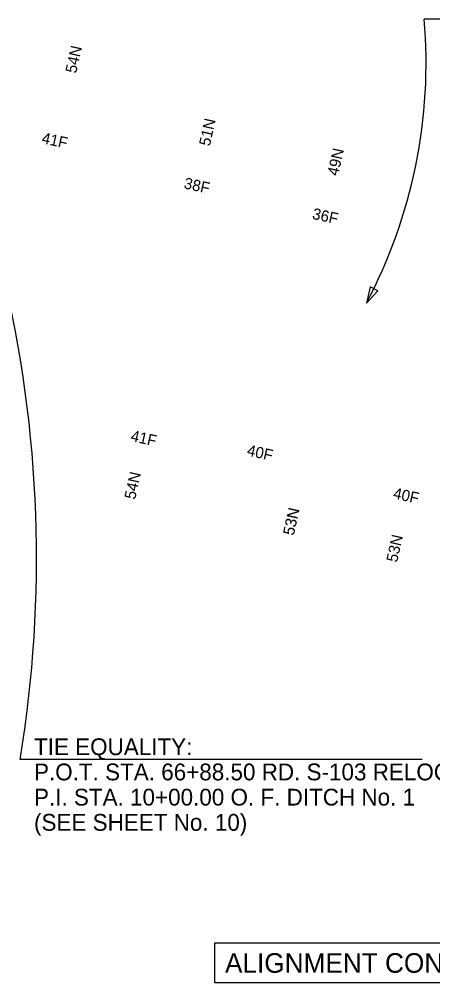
# Model space of a CAD drawing. Extents: x 1964849 to 1967422, y 1116563 to 1122210.
# Drawn here: x 1967021.8 to 1967169.6, y 1118230.2 to 1118574.2 of the extents above; entities that cross this region are included whole.
import ezdxf

# ---------------------------------------------------------------- set-up
doc = ezdxf.new("R2010")
doc.units = 0
for name, color, linetype in [('RD_HC_Data', 7, 'Continuous'), ('RD_PD_TX_CstnLmt', 7, 'Continuous'), ('RD_Sketch1', 7, 'Continuous'), ('RD_TX_Drainage', 7, 'Continuous'), ('RD_TX_Misc1', 7, 'Continuous')]:
    doc.layers.add(name, color=color, linetype=linetype)

msp = doc.modelspace()

# ---------------------------------------------------------------- linework, layer by layer
at = {"layer": 'RD_HC_Data'}
msp.add_line((1967165.81, 1118309.94), (1967022.08, 1118309.94), dxfattribs=at)
msp.add_arc((1966589.37, 1118381.72), 438.62, 350.5812, 13.5141, dxfattribs=at)
at = {"layer": 'RD_Sketch1'}
msp.add_lwpolyline([(1967091.71, 1118244.43), (1967392.13, 1118244.43), (1967392.13, 1118230.17), (1967091.71, 1118230.17)], close=True, dxfattribs=at)
at = {"layer": 'RD_TX_Misc1'}
msp.add_line((1967333.2, 1118574.21), (1967166.6, 1118574.21), dxfattribs=at)
msp.add_lwpolyline([(1967147.24, 1118478.67), (1967145.89, 1118472.82), (1967149.98, 1118477.21)], close=True, dxfattribs=at)
msp.add_arc((1966984.14, 1118558.66), 183.12, 332.0444, 4.8712, dxfattribs=at)

# ---------------------------------------------------------------- texts
at = {"layer": 'RD_HC_Data'}
for s, p in [('TIE EQUALITY:', (1967027.08, 1118311.44)), ('P.O.T. STA. 66+88.50 RD. S-103 RELOC. =', (1967027.08, 1118302.44)), ('P.I. STA. 10+00.00 O. F. DITCH No. 1', (1967027.08, 1118293.44)), ('(SEE SHEET No. 10)', (1967027.08, 1118284.44))]:
    msp.add_text(s, height=6, dxfattribs=at).set_placement(p)
at = {"layer": 'RD_PD_TX_CstnLmt'}
for s, p in [('41F', (1967029.58, 1118530.02)), ('38F', (1967080.42, 1118513.89)), ('36F', (1967126.32, 1118502.99)), ('41F', (1967061.4, 1118423.66)), ('40F', (1967102.97, 1118418.49)), ('40F', (1967155.23, 1118403.17))]:
    msp.add_text(s, height=4, rotation=347.4724, dxfattribs=at).set_placement(p)
at = {"layer": 'RD_Sketch1'}
msp.add_text('ALIGNMENT CONTROL CAN BE FOUND ON REFERENCE SHEET', height=7, dxfattribs=at).set_placement((1967095.36, 1118233.72))
at = {"layer": 'RD_TX_Drainage'}
for s, p in [('54N', (1967042.13, 1118554.7)), ('51N', (1967089.92, 1118528.71)), ('49N', (1967135.79, 1118518.08)), ('54N', (1967063.22, 1118402.53)), ('53N', (1967119.92, 1118389.67)), ('53N', (1967119.93, 1118389.72)), ('53N', (1967156.87, 1118380.09))]:
    msp.add_text(s, height=4, rotation=77.4724, dxfattribs=at).set_placement(p)

doc.saveas('drawing.dxf')
